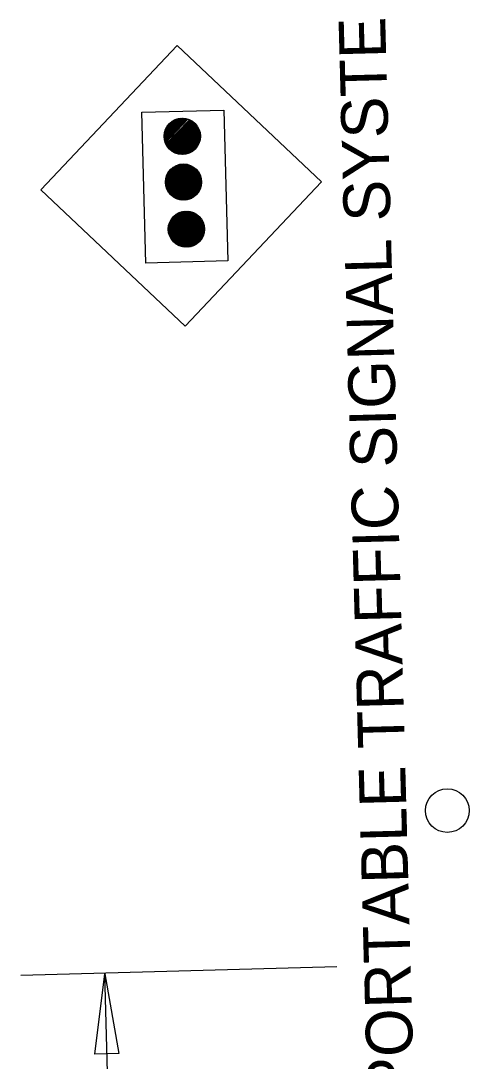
# Model space of a CAD drawing. Extents: x 1929624 to 1932070, y 596315 to 605533.
# Drawn here: x 1931266.5 to 1931324.1, y 596737.2 to 596871 of the extents above; entities that cross this region are included whole.
import ezdxf

# ---------------------------------------------------------------- set-up
doc = ezdxf.new("R2010")
doc.units = 0
doc.layers.add('Default', color=7, linetype='Continuous')

msp = doc.modelspace()

# ---------------------------------------------------------------- linework, layer by layer
at = {"layer": 'Default'}
for p, q in [((1931269.03, 596849.23), (1931286.55, 596867.78)), ((1931286.55, 596867.78), (1931305.1, 596850.26)), ((1931287.06, 596858.45), (1931284.89, 596856.16)), ((1931287.2, 596858.45), (1931284.89, 596856.02)), ((1931287.34, 596858.45), (1931284.9, 596855.88)), ((1931286.9, 596858.43), (1931284.9, 596856.32)), ((1931287.47, 596858.44), (1931284.92, 596855.75)), ((1931286.74, 596858.4), (1931284.92, 596856.49)), ((1931287.59, 596858.42), (1931284.94, 596855.63)), ((1931286.55, 596858.35), (1931284.96, 596856.67)), ((1931287.71, 596858.4), (1931284.97, 596855.51)), ((1931287.82, 596858.37), (1931285.01, 596855.4)), ((1931286.34, 596858.28), (1931285.02, 596856.88)), ((1931287.93, 596858.34), (1931285.05, 596855.29)), ((1931288.14, 596858.26), (1931285.13, 596855.09)), ((1931286.09, 596858.16), (1931285.13, 596857.15)), ((1931288.24, 596858.22), (1931285.18, 596855)), ((1931288.33, 596858.17), (1931285.24, 596854.9)), ((1931288.42, 596858.12), (1931285.29, 596854.82)), ((1931288.51, 596858.06), (1931285.35, 596854.73)), ((1931288.59, 596858), (1931285.42, 596854.65)), ((1931285.64, 596857.83), (1931285.43, 596857.61)), ((1931288.67, 596857.94), (1931285.48, 596854.57)), ((1931288.75, 596857.88), (1931285.55, 596854.5)), ((1931288.83, 596857.81), (1931285.62, 596854.43)), ((1931288.9, 596857.74), (1931285.7, 596854.36)), ((1931288.97, 596857.66), (1931285.78, 596854.3)), ((1931289.03, 596857.59), (1931285.86, 596854.24)), ((1931289.09, 596857.5), (1931285.94, 596854.18)), ((1931289.15, 596857.42), (1931286.03, 596854.12)), ((1931289.21, 596857.33), (1931286.12, 596854.07)), ((1931289.26, 596857.24), (1931286.21, 596854.02)), ((1931289.31, 596857.15), (1931286.31, 596853.98)), ((1931289.36, 596857.05), (1931286.41, 596853.94)), ((1931289.4, 596856.94), (1931286.52, 596853.9)), ((1931289.44, 596856.84), (1931286.63, 596853.87)), ((1931289.47, 596856.72), (1931286.74, 596853.84)), ((1931289.5, 596856.61), (1931286.86, 596853.82)), ((1931289.52, 596856.48), (1931286.99, 596853.81)), ((1931289.54, 596856.35), (1931287.12, 596853.8)), ((1931289.55, 596856.22), (1931287.25, 596853.8)), ((1931289.55, 596856.07), (1931287.4, 596853.8)), ((1931289.54, 596855.91), (1931287.55, 596853.82)), ((1931289.52, 596855.74), (1931287.72, 596853.85)), ((1931289.48, 596855.55), (1931287.91, 596853.9)), ((1931289.41, 596855.34), (1931288.12, 596853.98)), ((1931289.3, 596855.07), (1931288.39, 596854.11)), ((1931287.28, 596852.56), (1931285.05, 596850.21)), ((1931287.13, 596852.55), (1931285.05, 596850.36)), ((1931287.42, 596852.57), (1931285.06, 596850.07)), ((1931287.56, 596852.56), (1931285.07, 596849.94)), ((1931286.97, 596852.53), (1931285.07, 596850.52)), ((1931287.68, 596852.55), (1931285.09, 596849.81)), ((1931286.79, 596852.49), (1931285.1, 596850.7)), ((1931287.8, 596852.53), (1931285.11, 596849.69)), ((1931287.92, 596852.5), (1931285.15, 596849.57)), ((1931286.6, 596852.43), (1931285.15, 596850.9)), ((1931288.03, 596852.47), (1931285.18, 596849.46)), ((1931288.14, 596852.44), (1931285.22, 596849.36)), ((1931286.37, 596852.33), (1931285.23, 596851.14)), ((1931288.24, 596852.4), (1931285.27, 596849.26)), ((1931288.34, 596852.36), (1931285.31, 596849.16)), ((1931288.44, 596852.31), (1931285.36, 596849.07)), ((1931286.05, 596852.15), (1931285.39, 596851.46)), ((1931288.53, 596852.26), (1931285.42, 596848.98)), ((1931288.62, 596852.21), (1931285.48, 596848.89)), ((1931288.7, 596852.15), (1931285.54, 596848.81)), ((1931288.79, 596852.09), (1931285.6, 596848.73)), ((1931288.87, 596852.03), (1931285.67, 596848.66)), ((1931288.94, 596851.96), (1931285.74, 596848.58)), ((1931289.02, 596851.89), (1931285.81, 596848.51)), ((1931289.09, 596851.82), (1931285.89, 596848.45)), ((1931289.15, 596851.74), (1931285.97, 596848.38)), ((1931289.22, 596851.66), (1931286.05, 596848.32)), ((1931289.28, 596851.58), (1931286.14, 596848.27)), ((1931289.34, 596851.5), (1931286.23, 596848.21)), ((1931289.39, 596851.41), (1931286.32, 596848.16)), ((1931289.44, 596851.31), (1931286.41, 596848.12)), ((1931289.49, 596851.22), (1931286.51, 596848.07)), ((1931289.54, 596851.11), (1931286.62, 596848.04)), ((1931289.57, 596851.01), (1931286.72, 596848)), ((1931289.61, 596850.9), (1931286.84, 596847.97)), ((1931289.64, 596850.79), (1931286.95, 596847.95)), ((1931289.67, 596850.67), (1931287.07, 596847.93)), ((1931289.69, 596850.54), (1931287.2, 596847.92)), ((1931289.7, 596850.41), (1931287.33, 596847.91)), ((1931289.71, 596850.27), (1931287.47, 596847.91)), ((1931287.58, 596831.73), (1931305.1, 596850.26)), ((1931269.03, 596849.23), (1931287.58, 596831.73)), ((1931289.7, 596850.12), (1931287.62, 596847.92)), ((1931289.69, 596849.95), (1931287.79, 596847.94)), ((1931289.66, 596849.78), (1931287.96, 596847.98)), ((1931289.61, 596849.58), (1931288.16, 596848.04)), ((1931289.53, 596849.34), (1931288.39, 596848.14)), ((1931289.36, 596849.02), (1931288.7, 596848.32)), ((1931287.66, 596846.51), (1931285.43, 596844.15)), ((1931287.8, 596846.51), (1931285.43, 596844.01)), ((1931287.51, 596846.5), (1931285.43, 596844.3)), ((1931287.35, 596846.47), (1931285.44, 596844.47)), ((1931287.93, 596846.5), (1931285.45, 596843.88)), ((1931288.06, 596846.49), (1931285.47, 596843.75)), ((1931287.17, 596846.44), (1931285.47, 596844.64)), ((1931288.18, 596846.47), (1931285.49, 596843.63)), ((1931288.3, 596846.45), (1931285.52, 596843.52)), ((1931286.97, 596846.38), (1931285.52, 596844.84)), ((1931288.41, 596846.42), (1931285.56, 596843.41)), ((1931288.51, 596846.38), (1931285.6, 596843.3)), ((1931286.74, 596846.28), (1931285.61, 596845.08)), ((1931288.62, 596846.34), (1931285.64, 596843.2)), ((1931288.72, 596846.3), (1931285.69, 596843.11)), ((1931288.81, 596846.26), (1931285.74, 596843.01)), ((1931286.43, 596846.1), (1931285.77, 596845.4)), ((1931288.9, 596846.21), (1931285.79, 596842.92)), ((1931288.99, 596846.15), (1931285.85, 596842.84)), ((1931289.08, 596846.1), (1931285.91, 596842.76)), ((1931289.16, 596846.04), (1931285.98, 596842.68)), ((1931289.24, 596845.97), (1931286.05, 596842.6)), ((1931289.32, 596845.91), (1931286.12, 596842.53)), ((1931289.39, 596845.84), (1931286.19, 596842.46)), ((1931289.46, 596845.76), (1931286.27, 596842.39)), ((1931289.53, 596845.69), (1931286.35, 596842.33)), ((1931289.59, 596845.61), (1931286.43, 596842.27)), ((1931289.66, 596845.53), (1931286.51, 596842.21)), ((1931289.71, 596845.44), (1931286.6, 596842.16)), ((1931289.77, 596845.35), (1931286.69, 596842.11)), ((1931289.82, 596845.26), (1931286.79, 596842.06)), ((1931289.87, 596845.16), (1931286.89, 596842.02)), ((1931289.91, 596845.06), (1931286.99, 596841.98)), ((1931289.95, 596844.95), (1931287.1, 596841.95)), ((1931289.99, 596844.85), (1931287.21, 596841.92)), ((1931290.02, 596844.73), (1931287.33, 596841.89)), ((1931290.04, 596844.61), (1931287.45, 596841.87)), ((1931290.06, 596844.48), (1931287.58, 596841.86)), ((1931290.08, 596844.35), (1931287.71, 596841.85)), ((1931290.08, 596844.21), (1931287.85, 596841.86)), ((1931290.08, 596844.06), (1931288, 596841.87)), ((1931290.07, 596843.9), (1931288.16, 596841.89)), ((1931290.04, 596843.72), (1931288.34, 596841.93)), ((1931289.99, 596843.52), (1931288.53, 596841.99)), ((1931289.9, 596843.29), (1931288.76, 596842.08)), ((1931289.74, 596842.97), (1931289.07, 596842.26)), ((1931266.47, 596748.27), (1931307.09, 596749.36)), ((1931275.99, 596738.11), (1931277.26, 596748.45)), ((1931278.16, 596714.79), (1931277.26, 596748.45)), ((1931277.26, 596748.45), (1931279.08, 596738.19)), ((1931279.08, 596738.19), (1931275.99, 596738.11))]:
    msp.add_line(p, q, dxfattribs=at)
msp.add_lwpolyline([(1931293.07, 596840.09), (1931282.55, 596839.8), (1931282.03, 596859.22), (1931292.55, 596859.5)], close=True, dxfattribs=at)
for centre, radius in [((1931287.22, 596856.12), 2.33), ((1931287.38, 596850.24), 2.33), ((1931287.75, 596844.18), 2.33), ((1931321.29, 596769.43), 2.81)]:
    msp.add_circle(centre, radius, dxfattribs=at)

# ---------------------------------------------------------------- texts
msp.add_text('PORTABLE TRAFFIC SIGNAL SYSTEM', height=6, rotation=91.5377, dxfattribs=at).set_placement((1931317.03, 596732.48))

doc.saveas('drawing.dxf')
